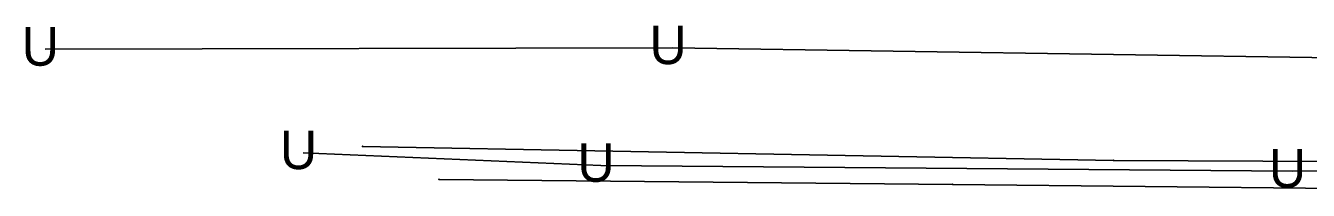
# Model space of a CAD drawing. Extents: x 1930288 to 1941089, y 588389 to 611475.
# Drawn here: x 1930288.4 to 1930488, y 598110.7 to 598136.4 of the extents above; entities that cross this region are included whole.
import ezdxf

# ---------------------------------------------------------------- set-up
doc = ezdxf.new("R2010")
doc.units = 0
for name, color, linetype in [('Default', 7, 'Continuous'), ('S_FENCE', 7, 'Continuous'), ('S_GAS_UTILITIES', 7, 'Continuous'), ('S_MSC_PT_SYM', 7, 'Continuous'), ('S_UNDERGROUND_CABLE', 7, 'Continuous'), ('S_UTL_PT_SYM', 7, 'Continuous')]:
    doc.layers.add(name, color=color, linetype=linetype)

msp = doc.modelspace()

# ---------------------------------------------------------------- linework, layer by layer
at = {"layer": 'S_FENCE'}
for p, q in [((1930352.69, 598112.42), (1930432.64, 598111.64)), ((1930432.64, 598111.64), (1930518.54, 598110.72))]:
    msp.add_line(p, q, dxfattribs=at)
at = {"layer": 'S_GAS_UTILITIES'}
for p, q in [((1930457.65, 598115.39), (1930340.79, 598117.56)), ((1930515.32, 598115.07), (1930457.65, 598115.39))]:
    msp.add_line(p, q, dxfattribs=at)
at = {"layer": 'S_MSC_PT_SYM'}
for points in [[(1930352.69, 598112.42), (1930352.69, 598112.47), (1930352.69, 598112.42), (1930352.64, 598112.42), (1930352.69, 598112.42), (1930352.69, 598112.37), (1930352.69, 598112.42), (1930352.74, 598112.42)], [(1930432.64, 598111.64), (1930432.64, 598111.69), (1930432.64, 598111.64), (1930432.59, 598111.64), (1930432.64, 598111.64), (1930432.64, 598111.59), (1930432.64, 598111.64), (1930432.69, 598111.64)]]:
    msp.add_lwpolyline(points, dxfattribs=at)
at = {"layer": 'S_UNDERGROUND_CABLE'}
for p, q in [((1930291.38, 598132.68), (1930389.07, 598132.91)), ((1930389.07, 598132.91), (1930491.94, 598131.38)), ((1930331.56, 598116.58), (1930377.85, 598114.6)), ((1930377.85, 598114.6), (1930485.45, 598113.69)), ((1930485.45, 598113.69), (1930562.39, 598114.47))]:
    msp.add_line(p, q, dxfattribs=at)
at = {"layer": 'S_UTL_PT_SYM'}
for points in [[(1930340.79, 598117.56), (1930340.79, 598117.61), (1930340.79, 598117.56), (1930340.74, 598117.56), (1930340.79, 598117.56), (1930340.79, 598117.51), (1930340.79, 598117.56), (1930340.84, 598117.56)], [(1930457.65, 598115.39), (1930457.65, 598115.44), (1930457.65, 598115.39), (1930457.6, 598115.39), (1930457.65, 598115.39), (1930457.65, 598115.34), (1930457.65, 598115.39), (1930457.7, 598115.39)]]:
    msp.add_lwpolyline(points, dxfattribs=at)

# ---------------------------------------------------------------- texts
at = {"layer": 'Default'}
for p in [(1930287.75, 598130.13), (1930385.44, 598130.37), (1930327.93, 598114.03), (1930374.22, 598112.05), (1930481.82, 598111.15)]:
    msp.add_text('U', height=6, rotation=360, dxfattribs=at).set_placement(p)

doc.saveas('drawing.dxf')
